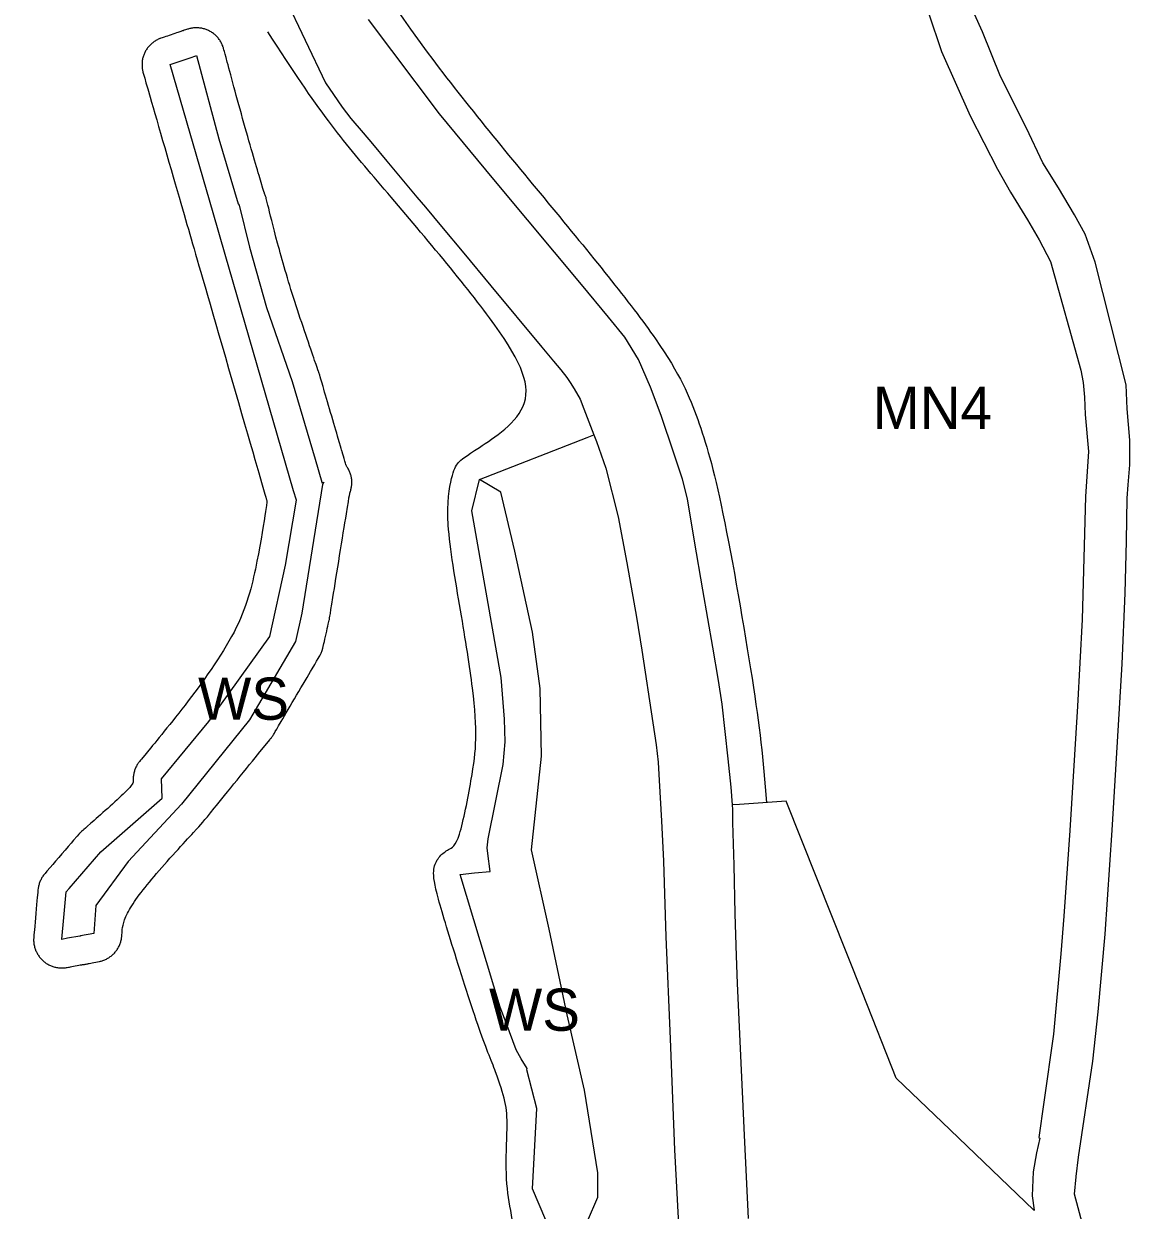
# Model space of a CAD drawing. Extents: x 7413438 to 7416393, y 5541665 to 5544118.
# Drawn here: x 7415451.4 to 7415609, y 5542207.5 to 5542376.1 of the extents above; entities that cross this region are included whole.
import ezdxf

# ---------------------------------------------------------------- set-up
doc = ezdxf.new("R2010")
doc.units = 0
for name, color, linetype in [('linie_rozgraniczajace', 7, 'Continuous'), ('linie_zabudowy_nieprzekraczalne', 7, 'Continuous'), ('oznaczenia_przeznaczen', 7, 'Continuous')]:
    doc.layers.add(name, color=color, linetype=linetype)

msp = doc.modelspace()

# ---------------------------------------------------------------- linework, layer by layer
at = {"layer": 'linie_rozgraniczajace'}
for p, q in [((7415486.42, 5542384.4), (7415494.32, 5542367.71)), ((7415587.7, 5542374.97), (7415585.68, 5542379.51)), ((7415503.74, 5542372.32), (7415500.43, 5542376.7)), ((7415580.03, 5542377.67), (7415581.9, 5542372.19)), ((7415590.29, 5542368.62), (7415587.7, 5542374.97)), ((7415475.1, 5542371.29), (7415475.88, 5542371.55)), ((7415475.88, 5542371.55), (7415475.99, 5542371.59)), ((7415475.99, 5542371.59), (7415479.17, 5542359.78)), ((7415510.52, 5542363.33), (7415503.74, 5542372.32)), ((7415581.9, 5542372.19), (7415585.98, 5542363.02)), ((7415472.25, 5542370.32), (7415475.1, 5542371.29)), ((7415478.35, 5542349.23), (7415472.25, 5542370.32)), ((7415593.96, 5542361.28), (7415590.29, 5542368.62)), ((7415494.32, 5542367.71), (7415495.46, 5542366.07)), ((7415495.46, 5542366.07), (7415496.7, 5542364.27)), ((7415496.7, 5542364.27), (7415497.95, 5542362.65)), ((7415518.24, 5542354), (7415510.52, 5542363.33)), ((7415585.98, 5542363.02), (7415589.86, 5542355.44)), ((7415497.95, 5542362.65), (7415499.68, 5542360.59)), ((7415479.17, 5542359.78), (7415481.92, 5542350.53)), ((7415499.68, 5542360.59), (7415500.99, 5542359.04)), ((7415596.3, 5542356.36), (7415593.96, 5542361.28)), ((7415500.99, 5542359.04), (7415503.06, 5542356.58)), ((7415503.06, 5542356.58), (7415504.24, 5542355.17)), ((7415598.53, 5542352.78), (7415596.3, 5542356.36)), ((7415504.24, 5542355.17), (7415507.32, 5542351.48)), ((7415589.86, 5542355.44), (7415591.72, 5542352.2)), ((7415523.02, 5542348.26), (7415518.24, 5542354)), ((7415507.32, 5542351.48), (7415508.53, 5542350.04)), ((7415591.72, 5542352.2), (7415594.13, 5542348.26)), ((7415600.82, 5542348.95), (7415598.53, 5542352.78)), ((7415481.92, 5542350.53), (7415482.05, 5542350.35)), ((7415482.05, 5542350.35), (7415483.51, 5542344.36)), ((7415508.53, 5542350.04), (7415510.81, 5542347.31)), ((7415480.06, 5542343.3), (7415478.35, 5542349.23)), ((7415530.7, 5542339.04), (7415523.02, 5542348.26)), ((7415594.13, 5542348.26), (7415595.76, 5542345.42)), ((7415602.32, 5542346.23), (7415600.82, 5542348.95)), ((7415510.81, 5542347.31), (7415514.01, 5542343.49)), ((7415603.72, 5542342.22), (7415602.32, 5542346.23)), ((7415595.76, 5542345.42), (7415597.41, 5542342.31)), ((7415489.77, 5542309.72), (7415480.06, 5542343.3)), ((7415483.51, 5542344.36), (7415485.96, 5542335.79)), ((7415514.01, 5542343.49), (7415517.85, 5542338.88)), ((7415597.41, 5542342.31), (7415601.69, 5542326.9)), ((7415608.14, 5542324.8), (7415603.72, 5542342.22)), ((7415517.85, 5542338.88), (7415525.1, 5542330.17)), ((7415534.54, 5542334.42), (7415530.7, 5542339.04)), ((7415485.96, 5542335.79), (7415489.61, 5542325.29)), ((7415536.87, 5542331.58), (7415534.54, 5542334.42)), ((7415538.82, 5542328.38), (7415536.87, 5542331.58)), ((7415525.1, 5542330.17), (7415526.73, 5542328.17)), ((7415526.73, 5542328.17), (7415527.76, 5542326.92)), ((7415540.53, 5542324.48), (7415538.82, 5542328.38)), ((7415527.76, 5542326.92), (7415528.63, 5542325.85)), ((7415601.69, 5542326.9), (7415602.03, 5542325.11)), ((7415489.61, 5542325.29), (7415492.86, 5542314.23)), ((7415528.63, 5542325.85), (7415529.13, 5542325.14)), ((7415529.13, 5542325.14), (7415529.67, 5542324.23)), ((7415529.67, 5542324.23), (7415530.52, 5542322.77)), ((7415542.02, 5542320.43), (7415540.53, 5542324.48)), ((7415602.03, 5542325.11), (7415602.22, 5542323.05)), ((7415608.29, 5542321.39), (7415608.14, 5542324.8)), ((7415530.52, 5542322.77), (7415531.06, 5542321.36)), ((7415602.22, 5542323.05), (7415602.32, 5542320.59)), ((7415531.06, 5542321.36), (7415532.47, 5542317.69)), ((7415608.65, 5542316.91), (7415608.29, 5542321.39)), ((7415543.83, 5542315.09), (7415542.02, 5542320.43)), ((7415602.32, 5542320.59), (7415602.79, 5542315.33)), ((7415531.54, 5542317.33), (7415532.47, 5542317.69)), ((7415532.47, 5542317.69), (7415532.83, 5542316.75)), ((7415516.21, 5542311.32), (7415531.54, 5542317.32)), ((7415531.54, 5542317.32), (7415531.54, 5542317.33)), ((7415532.83, 5542316.75), (7415534.19, 5542312.95)), ((7415608.65, 5542313.41), (7415608.65, 5542316.91)), ((7415492.86, 5542314.23), (7415493.79, 5542310.97)), ((7415545.09, 5542311.4), (7415543.83, 5542315.09)), ((7415602.79, 5542315.33), (7415602.37, 5542308.93)), ((7415534.19, 5542312.95), (7415535.91, 5542306.02)), ((7415608.41, 5542310.57), (7415608.65, 5542313.41)), ((7415493.79, 5542310.97), (7415493.82, 5542310.89)), ((7415493.82, 5542310.88), (7415494.08, 5542310.96)), ((7415493.82, 5542310.89), (7415493.82, 5542310.88)), ((7415494.08, 5542310.96), (7415493.91, 5542310.62)), ((7415515.13, 5542306.86), (7415516.21, 5542311.32)), ((7415519.23, 5542309.53), (7415516.21, 5542311.32)), ((7415545.77, 5542308.58), (7415545.09, 5542311.4)), ((7415490.18, 5542308.39), (7415489.77, 5542309.72)), ((7415493.91, 5542310.62), (7415490.98, 5542292.36)), ((7415521.26, 5542301.17), (7415519.23, 5542309.53)), ((7415608.31, 5542308.68), (7415608.41, 5542310.57)), ((7415488.62, 5542299.18), (7415490.18, 5542308.39)), ((7415546.8, 5542302.59), (7415545.77, 5542308.58)), ((7415602.37, 5542308.93), (7415601.89, 5542291.42)), ((7415608.18, 5542302.56), (7415608.31, 5542308.68)), ((7415517.33, 5542294.5), (7415515.13, 5542306.86)), ((7415535.91, 5542306.02), (7415537.17, 5542299.49)), ((7415547.98, 5542295.67), (7415546.8, 5542302.59)), ((7415608.02, 5542295.17), (7415608.18, 5542302.56)), ((7415523.77, 5542289.65), (7415521.26, 5542301.17)), ((7415486.41, 5542289.03), (7415488.62, 5542299.18)), ((7415537.17, 5542299.49), (7415538.53, 5542291.79)), ((7415549.38, 5542287.51), (7415547.98, 5542295.67)), ((7415519.3, 5542283.18), (7415517.33, 5542294.5)), ((7415607.59, 5542285.13), (7415608.02, 5542295.17)), ((7415490.98, 5542292.36), (7415490.07, 5542288.33)), ((7415538.53, 5542291.79), (7415539.3, 5542287.08)), ((7415601.89, 5542291.42), (7415601.22, 5542279.14)), ((7415477.76, 5542276.94), (7415486.41, 5542289.03)), ((7415524.85, 5542281.63), (7415523.77, 5542289.65)), ((7415490.07, 5542288.33), (7415483.5, 5542277.16)), ((7415550.19, 5542282.76), (7415549.38, 5542287.51)), ((7415539.3, 5542287.08), (7415540.87, 5542276.74)), ((7415606.92, 5542274.07), (7415607.59, 5542285.13)), ((7415519.76, 5542277.28), (7415519.3, 5542283.18)), ((7415550.71, 5542279.4), (7415550.19, 5542282.76)), ((7415525.03, 5542272), (7415524.85, 5542281.63)), ((7415551.58, 5542271.62), (7415550.71, 5542279.4)), ((7415601.22, 5542279.14), (7415600.14, 5542261.43)), ((7415483.5, 5542277.16), (7415473.84, 5542265.21)), ((7415519.89, 5542274.06), (7415519.76, 5542277.28)), ((7415471, 5542268.77), (7415477.76, 5542276.94)), ((7415540.87, 5542276.74), (7415541.34, 5542273.64)), ((7415519.59, 5542270.82), (7415519.89, 5542274.06)), ((7415541.34, 5542273.64), (7415541.63, 5542271.14)), ((7415606.16, 5542261.49), (7415606.92, 5542274.07)), ((7415523.63, 5542258.71), (7415525.03, 5542272)), ((7415517.43, 5542260.24), (7415519.59, 5542270.82)), ((7415541.63, 5542271.14), (7415541.77, 5542268.55)), ((7415551.98, 5542267.62), (7415551.58, 5542271.62)), ((7415471.11, 5542266.06), (7415471, 5542268.77)), ((7415541.77, 5542268.55), (7415542.09, 5542262.84)), ((7415552.16, 5542265.09), (7415551.98, 5542267.62)), ((7415462.37, 5542258.42), (7415471.11, 5542266.06)), ((7415473.84, 5542265.21), (7415466.29, 5542257.03)), ((7415559.81, 5542265.62), (7415553.19, 5542265.16)), ((7415570.65, 5542238.35), (7415559.81, 5542265.62)), ((7415553.19, 5542265.16), (7415552.16, 5542265.09)), ((7415552.21, 5542264.44), (7415552.16, 5542265.09)), ((7415552.25, 5542262.57), (7415552.21, 5542264.44)), ((7415542.09, 5542262.84), (7415542.39, 5542257.1)), ((7415552.4, 5542256.51), (7415552.25, 5542262.57)), ((7415517.3, 5542258.99), (7415517.43, 5542260.24)), ((7415600.14, 5542261.43), (7415599.29, 5542249.26)), ((7415605.14, 5542246.72), (7415606.16, 5542261.49)), ((7415517.4, 5542258.18), (7415517.3, 5542258.99)), ((7415526.13, 5542247.41), (7415523.63, 5542258.71)), ((7415457.89, 5542253.22), (7415462.37, 5542258.42)), ((7415466.29, 5542257.03), (7415461.68, 5542250.79)), ((7415517.73, 5542255.61), (7415517.4, 5542258.18)), ((7415542.39, 5542257.1), (7415542.71, 5542246.34)), ((7415513.48, 5542255.21), (7415515.53, 5542255.41)), ((7415519.16, 5542236.31), (7415513.48, 5542255.21)), ((7415515.53, 5542255.41), (7415517.73, 5542255.61)), ((7415552.57, 5542249.6), (7415552.4, 5542256.51)), ((7415457.12, 5542249.09), (7415457.45, 5542252.71)), ((7415457.45, 5542252.71), (7415457.89, 5542253.22)), ((7415461.68, 5542250.79), (7415461.39, 5542246.79)), ((7415456.84, 5542245.98), (7415457.12, 5542249.09)), ((7415552.77, 5542243.65), (7415552.57, 5542249.6)), ((7415599.29, 5542249.26), (7415598.86, 5542243.9)), ((7415461.39, 5542246.79), (7415459.51, 5542246.45)), ((7415528.67, 5542235.24), (7415526.13, 5542247.41)), ((7415604.15, 5542235.68), (7415605.14, 5542246.72)), ((7415456.85, 5542245.95), (7415456.84, 5542245.98)), ((7415457.65, 5542246.12), (7415456.85, 5542245.95)), ((7415459.42, 5542246.44), (7415457.65, 5542246.12)), ((7415459.52, 5542246.42), (7415459.42, 5542246.44)), ((7415459.51, 5542246.45), (7415459.52, 5542246.42)), ((7415542.71, 5542246.34), (7415543.3, 5542231.84)), ((7415552.91, 5542239.68), (7415552.77, 5542243.65)), ((7415598.86, 5542243.9), (7415597.81, 5542232.49)), ((7415553.9, 5542218.15), (7415552.91, 5542239.68)), ((7415575.46, 5542226.23), (7415570.65, 5542238.35)), ((7415520, 5542234.09), (7415519.16, 5542236.31)), ((7415531.15, 5542224.53), (7415528.67, 5542235.24)), ((7415603.41, 5542228.68), (7415604.15, 5542235.68)), ((7415521.45, 5542230.27), (7415520, 5542234.09)), ((7415543.3, 5542231.84), (7415543.95, 5542216.04)), ((7415597.81, 5542232.49), (7415596.46, 5542222.83)), ((7415522.12, 5542229), (7415521.45, 5542230.27)), ((7415522.98, 5542227.6), (7415522.12, 5542229)), ((7415601.36, 5542215.01), (7415603.41, 5542228.68)), ((7415522.96, 5542227.42), (7415522.98, 5542227.6)), ((7415524.37, 5542221.94), (7415522.96, 5542227.42)), ((7415583.14, 5542218.88), (7415575.46, 5542226.23)), ((7415533.03, 5542212.77), (7415531.15, 5542224.53)), ((7415523.76, 5542210.51), (7415524.37, 5542221.94)), ((7415596.46, 5542222.83), (7415595.75, 5542217.83)), ((7415554.48, 5542206.31), (7415553.9, 5542218.15)), ((7415595.02, 5542207.5), (7415583.14, 5542218.88)), ((7415595.88, 5542217.72), (7415595.42, 5542215.64)), ((7415595.75, 5542217.83), (7415595.88, 5542217.72)), ((7415543.95, 5542216.04), (7415544.6, 5542203.3)), ((7415595.42, 5542215.64), (7415594.94, 5542212.91)), ((7415601.06, 5542212.27), (7415601.36, 5542215.01)), ((7415594.94, 5542212.91), (7415594.79, 5542209.51)), ((7415533.06, 5542209.33), (7415533.03, 5542212.77)), ((7415600.78, 5542209.76), (7415601.05, 5542212.21)), ((7415601.05, 5542212.21), (7415601.06, 5542212.27)), ((7415525.66, 5542206.07), (7415523.76, 5542210.51)), ((7415601.32, 5542207.82), (7415600.78, 5542209.76)), ((7415531.58, 5542205.93), (7415533.06, 5542209.33)), ((7415594.79, 5542209.51), (7415595.08, 5542207.49)), ((7415595.08, 5542207.49), (7415595.02, 5542207.5)), ((7415595.08, 5542207.49), (7415595.09, 5542207.44)), ((7415601.9, 5542205.68), (7415601.32, 5542207.82))]:
    msp.add_line(p, q, dxfattribs=at)
at = {"layer": 'linie_zabudowy_nieprzekraczalne'}
for points in [[(7415295.99, 5542491.53), (7415302.85, 5542471.62), (7415308.05, 5542450.54), (7415314.21, 5542425.2), (7415323.86, 5542383.92), (7415331.41, 5542351.5), (7415333.83, 5542341.8), (7415336.46, 5542332.92), (7415338.78, 5542325.68), (7415342.46, 5542316.58), (7415345.14, 5542310.89), (7415347.54, 5542305.82), (7415350, 5542299.91), (7415352.77, 5542292.36), (7415355.49, 5542284.28), (7415358.59, 5542273.88), (7415361.68, 5542261.19), (7415364.65, 5542247.55), (7415369.56, 5542224.21), (7415371.28, 5542215.68), (7415372.37, 5542210.66), (7415373.22, 5542207.57), (7415375.86, 5542200.38), (7415379.74, 5542190.22), (7415382.99, 5542181.86), (7415385.67, 5542175.87), (7415392.06, 5542162.91), (7415396.28, 5542155.91), (7415400.54, 5542148.84), (7415409.48, 5542134.31), (7415416.95, 5542121.74), (7415427, 5542104.71), (7415427.44, 5542103.88), (7415430.21, 5542102.63), (7415445.54, 5542107.53), (7415455.72, 5542110.79), (7415466.45, 5542114.94), (7415481.49, 5542125.25), (7415498.78, 5542137.78), (7415505.24, 5542143.35), (7415506.64, 5542150.49), (7415507.47, 5542153.2), (7415507.59, 5542156.4), (7415509.01, 5542160.12), (7415514.59, 5542173.7), (7415516.59, 5542179.22), (7415519.53, 5542190.38), (7415521.31, 5542196.94), (7415521.5, 5542202.22), (7415520.65, 5542207.52), (7415519.83, 5542212.18), (7415520.24, 5542219.81), (7415520.01, 5542222.73), (7415518.69, 5542226.87), (7415516.28, 5542232.53), (7415511.98, 5542246.23), (7415509.64, 5542254.02), (7415509.63, 5542256.3), (7415510.53, 5542257.88), (7415511.79, 5542258.8), (7415513.31, 5542259.37), (7415515.21, 5542269.39), (7415515.87, 5542274.11), (7415515.45, 5542280.92), (7415513.62, 5542292.38), (7415511.18, 5542306.13), (7415512.31, 5542312.21), (7415513.08, 5542313.79), (7415514.76, 5542315.01), (7415525.18, 5542321.62), (7415520.14, 5542332.18), (7415500.04, 5542355.68), (7415493.33, 5542363.63), (7415486.15, 5542374.99)], [(7415899.76, 5542370.06), (7415890.5, 5542371.51), (7415890.18, 5542371.57), (7415842.61, 5542381.72), (7415842.54, 5542381.73), (7415842.41, 5542381.77), (7415802.64, 5542391.68), (7415802.56, 5542391.7), (7415799.82, 5542392.42), (7415790.68, 5542394.82), (7415790.68, 5542394.82), (7415772.53, 5542399.6), (7415754.12, 5542404.43), (7415753.97, 5542404.47), (7415740.38, 5542408.42), (7415736.95, 5542409.26), (7415737.33, 5542411.02), (7415726.72, 5542413.79), (7415726.34, 5542411.89), (7415704.45, 5542417.31), (7415694.73, 5542419.72), (7415670.48, 5542425.71), (7415651.75, 5542430.33), (7415649.18, 5542430.32), (7415618.58, 5542436.91), (7415611.16, 5542438.51), (7415611.15, 5542438.51), (7415606.13, 5542439.6), (7415585.02, 5542444.04), (7415584.99, 5542444.05), (7415570.36, 5542447.23), (7415564.82, 5542448.43), (7415564.92, 5542449.35), (7415557.02, 5542450.59), (7415551.9, 5542451.66), (7415551.7, 5542451.18), (7415543.32, 5542453.53), (7415530.6, 5542457.08), (7415530.59, 5542457.08), (7415527.99, 5542457.81), (7415524.72, 5542458.51), (7415520.86, 5542458.61), (7415520.47, 5542458.63), (7415520.11, 5542458.67), (7415506.46, 5542460.74), (7415493.13, 5542462.73), (7415493.09, 5542462.74), (7415492.77, 5542462.8), (7415490.79, 5542463.22)], [(7415497.47, 5542394.42), (7415498.09, 5542387.45), (7415507.76, 5542372.53), (7415526.12, 5542350.55), (7415543.48, 5542329.32), (7415547.36, 5542320.08), (7415550.51, 5542309.59), (7415555.55, 5542280.38), (7415556.54, 5542271.69), (7415557.02, 5542265.38)], [(7415452.83, 5542245.77), (7415452.83, 5542246.03), (7415452.84, 5542246.29), (7415453.45, 5542253.02), (7415453.48, 5542253.28), (7415453.53, 5542253.54), (7415453.6, 5542253.79), (7415453.68, 5542254.04), (7415453.78, 5542254.28), (7415453.89, 5542254.52), (7415454.02, 5542254.75), (7415454.16, 5542254.97), (7415454.32, 5542255.18), (7415454.4, 5542255.27), (7415459.32, 5542260.99), (7415459.41, 5542261.09), (7415459.6, 5542261.27), (7415459.72, 5542261.39), (7415467.02, 5542267.77), (7415466.99, 5542268.56), (7415466.98, 5542268.82), (7415467, 5542269.09), (7415467.03, 5542269.35), (7415467.08, 5542269.6), (7415467.15, 5542269.86), (7415467.23, 5542270.1), (7415467.33, 5542270.35), (7415467.44, 5542270.58), (7415467.57, 5542270.81), (7415467.71, 5542271.03), (7415467.87, 5542271.24), (7415467.9, 5542271.28), (7415474.58, 5542279.34), (7415482.66, 5542290.64), (7415484.68, 5542299.89), (7415486.06, 5542308.08), (7415485.93, 5542308.52), (7415485.91, 5542308.57), (7415476.21, 5542342.15), (7415474.49, 5542348.08), (7415468.39, 5542369.17), (7415468.35, 5542369.34), (7415468.29, 5542369.6), (7415468.26, 5542369.86), (7415468.24, 5542370.12), (7415468.24, 5542370.38), (7415468.25, 5542370.64), (7415468.28, 5542370.9), (7415468.33, 5542371.16), (7415468.4, 5542371.41), (7415468.48, 5542371.66), (7415468.58, 5542371.9), (7415468.69, 5542372.14), (7415468.82, 5542372.36), (7415468.97, 5542372.58), (7415469.12, 5542372.79), (7415469.29, 5542372.99), (7415469.48, 5542373.18), (7415469.67, 5542373.35), (7415469.88, 5542373.51), (7415470.1, 5542373.66), (7415470.32, 5542373.79), (7415470.56, 5542373.91), (7415470.8, 5542374.01), (7415470.95, 5542374.07), (7415473.8, 5542375.03), (7415473.81, 5542375.04), (7415474.7, 5542375.34), (7415474.79, 5542375.36), (7415475.04, 5542375.43), (7415475.29, 5542375.49), (7415475.55, 5542375.52), (7415475.81, 5542375.54), (7415476.08, 5542375.54), (7415476.34, 5542375.53), (7415476.6, 5542375.5), (7415476.85, 5542375.45), (7415477.11, 5542375.38), (7415477.36, 5542375.3), (7415477.6, 5542375.2), (7415477.83, 5542375.09), (7415478.06, 5542374.96), (7415478.28, 5542374.81), (7415478.49, 5542374.66), (7415478.69, 5542374.49), (7415478.87, 5542374.3), (7415479.05, 5542374.11), (7415479.21, 5542373.9), (7415479.36, 5542373.68), (7415479.49, 5542373.46), (7415479.61, 5542373.22), (7415479.71, 5542372.98), (7415479.8, 5542372.74), (7415479.84, 5542372.59), (7415483.01, 5542360.83), (7415485.58, 5542352.16), (7415485.66, 5542351.99), (7415485.76, 5542351.75), (7415485.85, 5542351.5), (7415485.92, 5542351.26), (7415487.36, 5542345.34), (7415489.76, 5542336.95), (7415493.38, 5542326.56), (7415493.42, 5542326.43), (7415493.44, 5542326.37), (7415496.68, 5542315.31), (7415496.69, 5542315.3), (7415496.69, 5542315.28), (7415497.25, 5542313.34), (7415497.3, 5542313.27), (7415497.45, 5542313.05), (7415497.58, 5542312.83), (7415497.7, 5542312.59), (7415497.8, 5542312.35), (7415497.89, 5542312.1), (7415497.96, 5542311.85), (7415498.01, 5542311.6), (7415498.05, 5542311.34), (7415498.07, 5542311.08), (7415498.07, 5542310.81), (7415498.05, 5542310.55), (7415498.02, 5542310.29), (7415497.97, 5542310.04), (7415497.91, 5542309.78), (7415497.82, 5542309.53), (7415497.75, 5542309.36), (7415494.92, 5542291.68), (7415494.87, 5542291.44), (7415494.87, 5542291.43), (7415493.95, 5542287.4), (7415493.89, 5542287.15), (7415493.81, 5542286.91), (7415493.71, 5542286.66), (7415493.59, 5542286.43), (7415493.5, 5542286.26), (7415486.94, 5542275.09), (7415486.9, 5542275.03), (7415486.76, 5542274.81), (7415486.6, 5542274.6), (7415486.6, 5542274.6), (7415476.93, 5542262.65), (7415476.76, 5542262.46), (7415469.36, 5542254.43), (7415465.57, 5542249.3), (7415465.37, 5542246.45), (7415465.36, 5542246.38), (7415465.33, 5542246.12), (7415465.28, 5542245.86), (7415465.21, 5542245.61), (7415465.13, 5542245.36), (7415465.03, 5542245.12), (7415464.92, 5542244.88), (7415464.79, 5542244.66), (7415464.65, 5542244.44), (7415464.49, 5542244.23), (7415464.32, 5542244.03), (7415464.13, 5542243.84), (7415463.94, 5542243.67), (7415463.73, 5542243.51), (7415463.51, 5542243.36), (7415463.29, 5542243.23), (7415463.06, 5542243.11), (7415462.81, 5542243.01), (7415462.57, 5542242.92), (7415462.32, 5542242.85), (7415462.08, 5542242.8), (7415460.74, 5542242.56), (7415460.69, 5542242.55), (7415460.44, 5542242.48), (7415460.18, 5542242.43), (7415459.93, 5542242.39), (7415459.66, 5542242.37), (7415459.66, 5542242.37), (7415458.42, 5542242.15), (7415457.7, 5542241.99), (7415457.52, 5542241.96), (7415457.26, 5542241.92), (7415457, 5542241.9), (7415456.74, 5542241.9), (7415456.48, 5542241.92), (7415456.22, 5542241.95), (7415455.96, 5542242), (7415455.71, 5542242.06), (7415455.46, 5542242.15), (7415455.22, 5542242.24), (7415454.98, 5542242.36), (7415454.75, 5542242.49), (7415454.53, 5542242.63), (7415454.33, 5542242.79), (7415454.13, 5542242.96), (7415453.94, 5542243.14), (7415453.77, 5542243.34), (7415453.61, 5542243.55), (7415453.46, 5542243.76), (7415453.33, 5542243.99), (7415453.21, 5542244.22), (7415453.18, 5542244.29), (7415453.16, 5542244.32), (7415453.09, 5542244.49), (7415453.01, 5542244.74), (7415452.94, 5542244.99), (7415452.88, 5542245.25), (7415452.85, 5542245.51), (7415452.83, 5542245.77)]]:
    msp.add_open_spline(points, degree=3, dxfattribs=at)

# ---------------------------------------------------------------- texts
at = {"layer": 'oznaczenia_przeznaczen'}
for s, p in [('MN4', (7415572.12, 5542318.53)), ('WS', (7415476.21, 5542277.19)), ('WS', (7415517.57, 5542232.98))]:
    msp.add_text(s, height=6, dxfattribs=at).set_placement(p)

doc.saveas('drawing.dxf')
